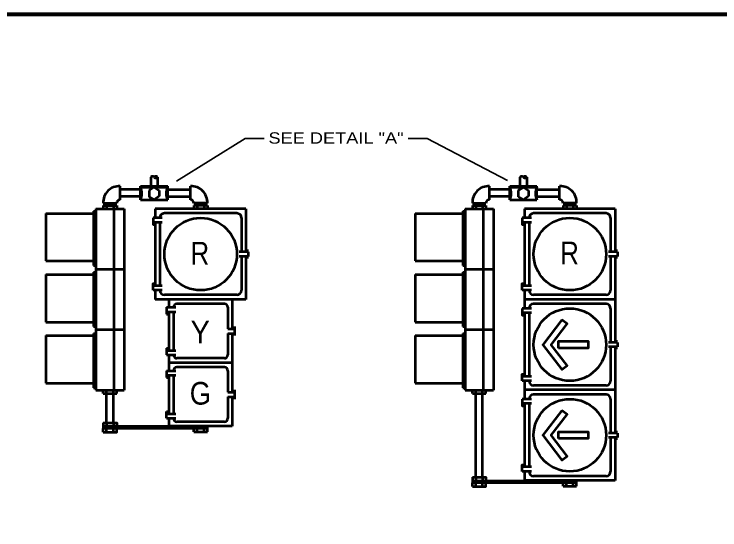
# Model space of a CAD drawing. Extents: x -382 to 473, y -132 to 412.
# Drawn here: x -265.8 to -78.9, y 269.1 to 405.8 of the extents above; entities that cross this region are included whole.
import ezdxf
from ezdxf.enums import TextEntityAlignment as Align

# ---------------------------------------------------------------- set-up
doc = ezdxf.new("R2010")
doc.units = 0
doc.header["$LTSCALE"] = 1.1
doc.layers.add('1', color=7, linetype='Continuous', lineweight=53)

msp = doc.modelspace()

# ---------------------------------------------------------------- linework, layer by layer
at = {"layer": '1', "lineweight": 35}
for p, q in [((-204.611, 372.79), (-222.839, 361.503)), ((-204.611, 372.79), (-199.62, 372.79)), ((-161.429, 372.79), (-156.438, 372.79)), ((-156.438, 372.79), (-135.173, 361.72))]:
    msp.add_line(p, q, dxfattribs=at)
at = {"layer": '1'}
for p, q in [((-229.64, 362.584), (-229.64, 360.184)), ((-227.84, 362.584), (-227.84, 360.184)), ((-131.84, 362.584), (-131.84, 360.184)), ((-130.04, 362.584), (-130.04, 360.184)), ((-237.74, 356.584), (-237.74, 360.184)), ((-232.34, 359.284), (-237.74, 359.284)), ((-232.34, 360.184), (-225.14, 360.184)), ((-232.34, 359.884), (-225.14, 359.884)), ((-228.74, 359.884), (-230.09, 359.074)), ((-230.09, 359.074), (-230.09, 357.394)), ((-228.74, 359.884), (-227.39, 359.074)), ((-227.39, 359.074), (-227.39, 357.514)), ((-225.14, 356.584), (-225.14, 360.184)), ((-225.128, 359.294), (-219.128, 359.294)), ((-219.128, 356.594), (-219.128, 360.194)), ((-139.94, 356.584), (-139.94, 360.184)), ((-134.54, 359.284), (-139.94, 359.284)), ((-134.54, 360.184), (-127.34, 360.184)), ((-134.54, 359.884), (-127.34, 359.884)), ((-130.94, 359.884), (-132.29, 359.074)), ((-132.29, 359.074), (-132.29, 357.394)), ((-130.94, 359.884), (-129.59, 359.074)), ((-129.59, 359.074), (-129.59, 357.514)), ((-127.34, 356.584), (-127.34, 360.184)), ((-127.328, 359.294), (-121.328, 359.294)), ((-121.328, 356.594), (-121.328, 360.194)), ((-232.34, 357.484), (-237.74, 357.484)), ((-230.09, 357.394), (-228.74, 356.584)), ((-227.39, 357.514), (-228.74, 356.584)), ((-225.128, 357.494), (-219.128, 357.494)), ((-134.54, 357.484), (-139.94, 357.484)), ((-132.29, 357.394), (-130.94, 356.584)), ((-129.59, 357.514), (-130.94, 356.584)), ((-127.328, 357.494), (-121.328, 357.494)), ((-242.24, 355.684), (-238.64, 355.684)), ((-241.34, 355.684), (-241.34, 354.184)), ((-239.54, 355.684), (-239.54, 354.184)), ((-232.34, 356.584), (-225.14, 356.584)), ((-214.628, 355.694), (-218.228, 355.694)), ((-217.328, 355.694), (-217.328, 354.194)), ((-215.528, 355.694), (-215.528, 354.194)), ((-144.44, 355.684), (-140.84, 355.684)), ((-143.54, 355.684), (-143.54, 354.184)), ((-141.74, 355.684), (-141.74, 354.184)), ((-134.54, 356.584), (-127.34, 356.584)), ((-116.828, 355.694), (-120.428, 355.694)), ((-119.528, 355.694), (-119.528, 354.194)), ((-117.728, 355.694), (-117.728, 354.194)), ((-244.79, 353.584), (-244.79, 339.184)), ((-244.79, 353.584), (-244.19, 353.584)), ((-244.19, 354.184), (-244.19, 306.184)), ((-244.19, 354.184), (-236.69, 354.184)), ((-242.24, 355.084), (-242.24, 354.184)), ((-242.24, 355.084), (-238.64, 355.084)), ((-239.39, 353.884), (-239.39, 306.484)), ((-238.64, 355.084), (-238.64, 354.184)), ((-236.69, 354.184), (-236.69, 306.184)), ((-204.428, 354.194), (-228.428, 354.194)), ((-228.428, 354.194), (-228.428, 351.794)), ((-218.228, 355.094), (-218.228, 354.194)), ((-214.628, 355.094), (-218.228, 355.094)), ((-214.628, 355.094), (-214.628, 354.194)), ((-204.428, 354.194), (-204.428, 342.794)), ((-146.99, 353.584), (-146.99, 339.184)), ((-146.99, 353.584), (-146.39, 353.584)), ((-146.39, 354.184), (-146.39, 306.184)), ((-146.39, 354.184), (-138.89, 354.184)), ((-144.44, 355.084), (-144.44, 354.184)), ((-144.44, 355.084), (-140.84, 355.084)), ((-141.59, 353.884), (-141.59, 306.484)), ((-140.84, 355.084), (-140.84, 354.184)), ((-138.89, 354.184), (-138.89, 306.184)), ((-106.628, 354.194), (-130.628, 354.194)), ((-130.628, 354.194), (-130.628, 351.794)), ((-120.428, 355.094), (-120.428, 354.194)), ((-116.828, 355.094), (-120.428, 355.094)), ((-116.828, 355.094), (-116.828, 354.194)), ((-106.628, 354.194), (-106.628, 342.794)), ((-257.39, 352.984), (-244.79, 352.984)), ((-257.39, 352.984), (-257.39, 340.384)), ((-226.628, 351.794), (-229.028, 351.794)), ((-206.828, 352.994), (-226.028, 352.994)), ((-205.628, 351.794), (-205.628, 342.794)), ((-159.59, 352.984), (-146.99, 352.984)), ((-159.59, 352.984), (-159.59, 340.384)), ((-128.828, 351.794), (-131.228, 351.794)), ((-109.028, 352.994), (-128.228, 352.994)), ((-107.828, 351.794), (-107.828, 342.794)), ((-226.628, 350.594), (-229.028, 350.594)), ((-228.428, 350.594), (-228.428, 333.794)), ((-227.228, 350.594), (-227.228, 333.794)), ((-128.828, 350.594), (-131.228, 350.594)), ((-130.628, 350.594), (-130.628, 333.794)), ((-129.428, 350.594), (-129.428, 333.794)), ((-203.828, 342.794), (-206.228, 342.794)), ((-204.128, 343.394), (-204.128, 342.794)), ((-203.828, 342.794), (-203.828, 341.594)), ((-106.028, 342.794), (-108.428, 342.794)), ((-106.328, 343.394), (-106.328, 342.794)), ((-106.028, 342.794), (-106.028, 341.594)), ((-257.39, 340.384), (-244.79, 340.384)), ((-203.828, 341.594), (-206.228, 341.594)), ((-205.628, 341.594), (-205.628, 332.594)), ((-204.428, 341.594), (-204.428, 330.194)), ((-204.128, 341.594), (-204.128, 340.994)), ((-159.59, 340.384), (-146.99, 340.384)), ((-106.028, 341.594), (-108.428, 341.594)), ((-107.828, 341.594), (-107.828, 332.594)), ((-106.628, 341.594), (-106.628, 330.194)), ((-106.328, 341.594), (-106.328, 340.994)), ((-244.79, 339.184), (-244.19, 339.184)), ((-146.99, 339.184), (-146.39, 339.184)), ((-257.39, 336.784), (-244.79, 336.784)), ((-257.39, 336.784), (-257.39, 324.184)), ((-244.79, 337.384), (-244.79, 322.984)), ((-244.79, 337.384), (-244.19, 337.384)), ((-244.19, 338.188), (-236.69, 338.188)), ((-159.59, 336.784), (-146.99, 336.784)), ((-159.59, 336.784), (-159.59, 324.184)), ((-146.99, 337.384), (-146.99, 322.984)), ((-146.99, 337.384), (-146.39, 337.384)), ((-146.39, 338.188), (-138.89, 338.188)), ((-226.628, 333.794), (-229.028, 333.794)), ((-128.828, 333.794), (-131.228, 333.794)), ((-226.628, 332.594), (-229.028, 332.594)), ((-228.428, 332.594), (-228.428, 330.194)), ((-206.828, 331.394), (-226.028, 331.394)), ((-128.828, 332.594), (-131.228, 332.594)), ((-130.628, 332.594), (-130.628, 330.194)), ((-109.028, 331.394), (-128.228, 331.394)), ((-204.428, 330.194), (-228.428, 330.194)), ((-224.828, 330.194), (-224.828, 328.094)), ((-208.028, 330.194), (-208.028, 322.394)), ((-106.628, 330.194), (-130.628, 330.194)), ((-130.628, 330.194), (-130.628, 327.794)), ((-106.628, 330.194), (-106.628, 318.794)), ((-225.428, 328.094), (-223.028, 328.094)), ((-225.428, 328.094), (-225.428, 326.294)), ((-210.128, 328.994), (-222.728, 328.994)), ((-209.228, 328.094), (-209.228, 322.394)), ((-128.828, 327.794), (-131.228, 327.794)), ((-109.028, 328.994), (-128.228, 328.994)), ((-107.828, 327.794), (-107.828, 318.794)), ((-225.428, 326.894), (-223.028, 326.894)), ((-225.428, 326.294), (-224.828, 326.294)), ((-224.828, 326.894), (-224.828, 316.694)), ((-223.628, 326.894), (-223.628, 316.694)), ((-128.828, 326.594), (-131.228, 326.594)), ((-130.628, 326.594), (-130.628, 309.794)), ((-129.428, 326.594), (-129.428, 309.794)), ((-257.39, 324.184), (-244.79, 324.184)), ((-159.59, 324.184), (-146.99, 324.184)), ((-244.79, 322.984), (-244.19, 322.984)), ((-244.19, 322.18), (-236.69, 322.18)), ((-209.228, 322.394), (-207.428, 322.394)), ((-207.428, 322.994), (-207.428, 320.594)), ((-146.99, 322.984), (-146.39, 322.984)), ((-146.39, 322.18), (-138.89, 322.18)), ((-257.39, 320.584), (-257.008, 320.6)), ((-257.39, 320.584), (-244.79, 320.584)), ((-257.39, 320.584), (-257.39, 307.984)), ((-244.79, 321.184), (-244.79, 306.784)), ((-244.79, 321.184), (-244.19, 321.184)), ((-209.228, 321.194), (-207.428, 321.194)), ((-209.228, 321.194), (-209.228, 315.494)), ((-208.028, 321.194), (-208.028, 305.594)), ((-159.59, 320.584), (-159.208, 320.6)), ((-159.59, 320.584), (-146.99, 320.584)), ((-159.59, 320.584), (-159.59, 307.984)), ((-146.99, 321.184), (-146.99, 306.784)), ((-146.99, 321.184), (-146.39, 321.184)), ((-106.028, 318.794), (-108.428, 318.794)), ((-106.328, 319.394), (-106.328, 318.794)), ((-106.028, 318.794), (-106.028, 317.594)), ((-225.428, 317.294), (-225.428, 315.494)), ((-225.428, 317.294), (-224.828, 317.294)), ((-225.428, 316.694), (-223.028, 316.694)), ((-106.028, 317.594), (-108.428, 317.594)), ((-107.828, 317.594), (-107.828, 308.594)), ((-106.628, 317.594), (-106.628, 306.194)), ((-106.328, 317.594), (-106.328, 316.994)), ((-225.428, 315.494), (-223.028, 315.494)), ((-224.828, 315.494), (-224.828, 311.294)), ((-210.128, 314.594), (-222.728, 314.594)), ((-208.028, 313.394), (-224.828, 313.394)), ((-210.128, 312.194), (-222.728, 312.194)), ((-225.428, 311.294), (-223.028, 311.294)), ((-225.428, 311.294), (-225.428, 309.494)), ((-209.228, 311.294), (-209.228, 305.594)), ((-225.428, 310.094), (-223.028, 310.094)), ((-225.428, 309.494), (-224.828, 309.494)), ((-224.828, 310.094), (-224.828, 299.894)), ((-223.628, 310.094), (-223.628, 299.894)), ((-128.828, 309.794), (-131.228, 309.794)), ((-128.828, 308.594), (-131.228, 308.594)), ((-130.628, 308.594), (-130.628, 306.194)), ((-257.39, 307.984), (-244.79, 307.984)), ((-244.79, 306.784), (-244.19, 306.784)), ((-159.59, 307.984), (-146.99, 307.984)), ((-146.99, 306.784), (-146.39, 306.784)), ((-109.028, 307.394), (-128.228, 307.394)), ((-244.19, 306.184), (-236.69, 306.184)), ((-242.24, 305.29), (-242.24, 306.19)), ((-242.24, 305.29), (-238.64, 305.29)), ((-238.64, 305.29), (-238.64, 306.19)), ((-209.228, 305.594), (-207.428, 305.594)), ((-207.428, 306.194), (-207.428, 303.794)), ((-146.39, 306.184), (-138.89, 306.184)), ((-144.44, 305.29), (-144.44, 306.19)), ((-144.44, 305.29), (-140.84, 305.29)), ((-140.84, 305.29), (-140.84, 306.19)), ((-106.628, 306.194), (-130.628, 306.194)), ((-130.628, 306.194), (-130.628, 303.794)), ((-109.028, 304.994), (-128.228, 304.994)), ((-106.628, 306.194), (-106.628, 294.794)), ((-209.228, 304.394), (-207.428, 304.394)), ((-209.228, 304.394), (-209.228, 298.694)), ((-208.028, 304.394), (-208.028, 296.594)), ((-128.828, 303.794), (-131.228, 303.794)), ((-107.828, 303.794), (-107.828, 294.794)), ((-128.828, 302.594), (-131.228, 302.594)), ((-130.628, 302.594), (-130.628, 285.794)), ((-129.428, 302.594), (-129.428, 285.794)), ((-225.428, 298.694), (-225.428, 300.494)), ((-225.428, 300.494), (-224.828, 300.494)), ((-225.428, 299.894), (-223.028, 299.894)), ((-241.34, 297.465), (-241.34, 296.474)), ((-239.54, 297.465), (-239.54, 296.474)), ((-225.428, 298.694), (-223.028, 298.694)), ((-224.828, 298.694), (-224.828, 296.594)), ((-210.128, 297.794), (-222.728, 297.794)), ((-214.628, 296.474), (-242.24, 296.474)), ((-242.24, 295.004), (-242.24, 295.995)), ((-214.628, 295.994), (-242.24, 295.994)), ((-241.34, 295.004), (-241.34, 295.995)), ((-239.54, 295.004), (-239.54, 295.995)), ((-208.028, 296.594), (-224.828, 296.594)), ((-218.228, 295.094), (-218.228, 295.994)), ((-217.328, 295.094), (-217.328, 295.994)), ((-215.528, 295.094), (-215.528, 295.994)), ((-214.628, 295.094), (-214.628, 296.594)), ((-106.328, 295.394), (-106.328, 294.794)), ((-218.228, 295.094), (-214.628, 295.094)), ((-106.028, 294.794), (-108.428, 294.794)), ((-106.028, 293.594), (-108.428, 293.594)), ((-107.828, 293.594), (-107.828, 284.594)), ((-106.628, 293.594), (-106.628, 282.194)), ((-106.328, 293.594), (-106.328, 292.994)), ((-106.028, 294.794), (-106.028, 293.594)), ((-128.828, 285.794), (-131.228, 285.794)), ((-128.828, 284.594), (-131.228, 284.594)), ((-130.628, 284.594), (-130.628, 282.194)), ((-143.54, 283.065), (-143.54, 282.074)), ((-141.74, 283.065), (-141.74, 282.074)), ((-109.028, 283.394), (-128.228, 283.394)), ((-116.828, 282.074), (-144.44, 282.074)), ((-144.44, 280.604), (-144.44, 281.595)), ((-116.828, 281.594), (-144.44, 281.594)), ((-143.54, 280.604), (-143.54, 281.595)), ((-141.74, 280.604), (-141.74, 281.595)), ((-106.628, 282.194), (-130.628, 282.194)), ((-120.428, 280.694), (-120.428, 281.594)), ((-120.428, 280.694), (-116.828, 280.694)), ((-119.528, 280.694), (-119.528, 281.594)), ((-117.728, 280.694), (-117.728, 281.594)), ((-116.828, 280.694), (-116.828, 282.194))]:
    msp.add_line(p, q, dxfattribs=at)
at = {"layer": '1', "lineweight": 158}
msp.add_lwpolyline([(466.693, 405.773), (-325.007, 405.673), (-324.907, -120.327)], dxfattribs=at)
at = {"layer": '1'}
for points in [[(-232.34, 356.584), (-232.34, 359.884), (-232.34, 360.184)], [(-134.54, 356.584), (-134.54, 359.884), (-134.54, 360.184)], [(-229.028, 351.794), (-229.028, 349.994), (-228.428, 349.994)], [(-131.228, 351.794), (-131.228, 349.994), (-130.628, 349.994)], [(-229.028, 332.594), (-229.028, 334.394), (-228.428, 334.394)], [(-131.228, 332.594), (-131.228, 334.394), (-130.628, 334.394)], [(-131.228, 327.794), (-131.228, 325.994), (-130.628, 325.994)], [(-131.228, 308.594), (-131.228, 310.394), (-130.628, 310.394)], [(-241.34, 297.49), (-241.34, 305.29), (-241.34, 306.19)], [(-239.54, 297.49), (-239.54, 305.29), (-239.54, 306.19)], [(-143.54, 283.065), (-143.54, 305.29), (-143.54, 306.19)], [(-141.74, 283.065), (-141.74, 305.29), (-141.74, 306.19)], [(-131.228, 303.794), (-131.228, 301.994), (-130.628, 301.994)], [(-242.24, 297.465), (-238.64, 297.465), (-238.64, 296.474)], [(-242.24, 297.465), (-242.24, 296.474), (-242.24, 295.994)], [(-242.24, 295.004), (-238.64, 295.004), (-238.64, 295.995)], [(-131.228, 284.594), (-131.228, 286.394), (-130.628, 286.394)], [(-144.44, 283.065), (-140.84, 283.065), (-140.84, 282.074)], [(-144.44, 283.065), (-144.44, 282.074), (-144.44, 281.594)], [(-144.44, 280.604), (-140.84, 280.604), (-140.84, 281.595)]]:
    msp.add_lwpolyline(points, dxfattribs=at)
for points in [[(-120.791, 324.794), (-125.817, 318.194), (-120.787, 311.594), (-119.355, 312.685), (-123.555, 318.195), (-119.359, 323.704)], [(-121.617, 317.294), (-121.617, 319.094), (-113.817, 319.094), (-113.817, 317.294)], [(-120.791, 300.794), (-125.817, 294.194), (-120.787, 287.594), (-119.355, 288.685), (-123.555, 294.195), (-119.359, 299.704)], [(-121.617, 293.294), (-121.617, 295.094), (-113.817, 295.094), (-113.817, 293.294)]]:
    msp.add_lwpolyline(points, close=True, dxfattribs=at)
for centre in [(-216.417, 342.196), (-118.617, 342.196), (-118.617, 318.196), (-118.617, 294.196)]:
    msp.add_circle(centre, 9.6, dxfattribs=at)
for centre, radius, start, end in [((-229.19, 362.164), 0.616, 43.04811, 136.95189), ((-228.29, 362.164), 0.616, 43.04811, 136.95189), ((-131.39, 362.164), 0.616, 43.04811, 136.95189), ((-130.49, 362.164), 0.616, 43.04811, 136.95189), ((-228.29, 363), 0.616, 223.04811, 316.95189), ((-130.49, 363), 0.616, 223.04811, 316.95189), ((-237.93, 355.873), 4.315, 87.48391, 182.51609), ((-236.003, 358.234), 4.017, 335.74702, 24.25298), ((-221.515, 358.234), 4.017, 155.74702, 204.25298), ((-218.939, 355.883), 4.315, 357.48391, 92.51609), ((-140.13, 355.873), 4.315, 87.48391, 182.51609), ((-138.203, 358.234), 4.017, 335.74702, 24.25298), ((-123.715, 358.234), 4.017, 155.74702, 204.25298), ((-121.139, 355.883), 4.315, 357.48391, 92.51609), ((-237.784, 355.728), 0.857, 87.04875, 182.95125), ((-219.084, 355.738), 0.857, 357.04875, 92.95125), ((-139.984, 355.728), 0.857, 87.04875, 182.95125), ((-121.284, 355.738), 0.857, 357.04875, 92.95125), ((-226.028, 351.794), 1.2, 90, 180), ((-206.828, 351.794), 1.2, 0, 90), ((-128.228, 351.794), 1.2, 90, 180), ((-109.028, 351.794), 1.2, 0, 90), ((-226.028, 332.594), 1.2, 180, 270), ((-206.828, 332.594), 1.2, 270, 0), ((-128.228, 332.594), 1.2, 180, 270), ((-109.028, 332.594), 1.2, 270, 0), ((-222.728, 328.094), 0.9, 90, 180), ((-210.128, 328.094), 0.9, 0, 90), ((-128.228, 327.794), 1.2, 90, 180), ((-109.028, 327.794), 1.2, 0, 90), ((-222.728, 315.494), 0.9, 180, 270), ((-210.128, 315.494), 0.9, 270, 0), ((-222.728, 311.294), 0.9, 90, 180), ((-210.128, 311.294), 0.9, 0, 90), ((-128.228, 308.594), 1.2, 180, 270), ((-109.028, 308.594), 1.2, 270, 0), ((-128.228, 303.794), 1.2, 90, 180), ((-109.028, 303.794), 1.2, 0, 90), ((-222.728, 298.694), 0.9, 180, 270), ((-210.128, 298.694), 0.9, 270, 0), ((-128.228, 284.594), 1.2, 180, 270), ((-109.028, 284.594), 1.2, 270, 0)]:
    msp.add_arc(centre, radius, start, end, dxfattribs=at)

# ---------------------------------------------------------------- texts
at = {"layer": '1', "width": 1.2}
msp.add_text('SEE DETAIL "A"', height=3, dxfattribs=at).set_placement((-180.56, 371.457), align=Align.CENTER)
at = {"layer": '1'}
for s, width, p in [('R', 0.85, (-219.089, 339.435)), ('R', 0.85, (-121.16, 339.482)), ('Y', 0.95, (-219.071, 318.534)), ('G', 0.9, (-219.305, 302.312))]:
    msp.add_text(s, height=6, dxfattribs=dict(at, width=width)).set_placement(p)

doc.saveas('drawing.dxf')
